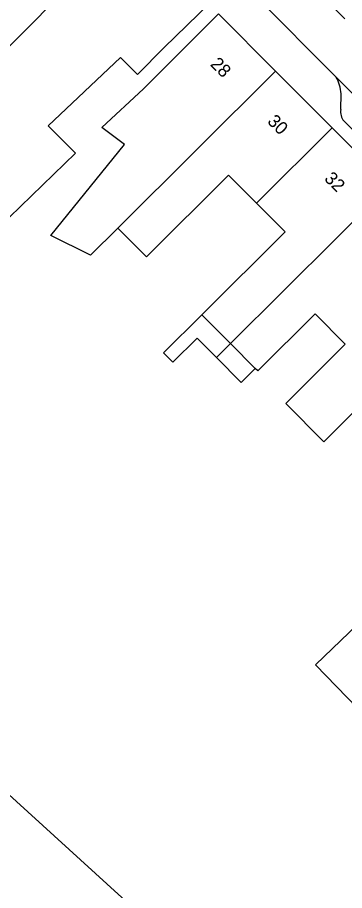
# Model space of a CAD drawing. Extents: x 160107 to 160928, y 382056 to 382918.
# Drawn here: x 160757.6 to 160782.8, y 382664.5 to 382731.9 of the extents above; entities that cross this region are included whole.
import ezdxf

# ---------------------------------------------------------------- set-up
doc = ezdxf.new("R2010")
doc.units = 0
for name, color, linetype in [('IMGEO_Pand', 7, 'Continuous'), ('IMGEO_Pand_nummerreeks', 7, 'Continuous'), ('IMGEO_Rijbaan_lokaal_open', 7, 'Continuous'), ('IMGEO_Voetpad_open', 7, 'Continuous')]:
    doc.layers.add(name, color=color, linetype=linetype)

msp = doc.modelspace()

# ---------------------------------------------------------------- linework, layer by layer
at = {"layer": 'IMGEO_Pand'}
for points in [[(160764.24, 382737.062), (160754.525, 382727.294)], [(160772.42, 382733.035), (160768.898, 382729.596), (160766.833, 382727.519), (160765.518, 382728.827), (160759.935, 382723.549), (160762.058, 382721.439), (160754.39, 382714.036), (160747.829, 382720.785), (160752.573, 382725.396)], [(160765.325, 382715.66), (160763.224, 382713.568), (160760.151, 382715.087), (160765.841, 382722.115), (160764.083, 382723.432), (160767.295, 382726.41), (160769.641, 382728.746), (160773.112, 382732.203)], [(160773.112, 382732.203), (160777.507, 382727.789)], [(160765.325, 382715.66), (160777.507, 382727.789)], [(160777.507, 382727.789), (160781.87, 382723.407)], [(160781.87, 382723.407), (160776.027, 382717.589)], [(160781.87, 382723.407), (160786.299, 382718.959)], [(160776.027, 382717.589), (160773.877, 382719.748), (160767.538, 382713.437), (160765.325, 382715.66)], [(160786.299, 382718.959), (160774.026, 382706.739)], [(160771.813, 382708.961), (160778.244, 382715.363), (160776.027, 382717.589)], [(160772.944, 382705.661), (160771.446, 382707.166), (160769.568, 382705.296), (160768.853, 382706.014), (160771.813, 382708.961)], [(160774.026, 382706.739), (160771.813, 382708.961)], [(160782.896, 382706.698), (160780.563, 382709.041), (160776.129, 382704.626), (160775.945, 382704.811)], [(160795.983, 382709.146), (160790.192, 382703.379), (160788.26, 382705.349), (160786.899, 382703.994), (160785.746, 382705.151), (160784.659, 382704.069), (160785.41, 382703.315), (160781.245, 382699.163), (160778.301, 382702.117), (160780.645, 382704.454), (160782.896, 382706.698)], [(160774.026, 382706.739), (160772.944, 382705.661)], [(160775.945, 382704.811), (160774.026, 382706.739)], [(160775.945, 382704.811), (160774.863, 382703.733), (160772.944, 382705.661)], [(160730.83, 382683.568), (160736.85, 382690.176), (160769.696, 382660.249), (160763.676, 382653.641), (160730.83, 382683.568)], [(160783.828, 382685.04), (160787.066, 382681.691), (160783.843, 382678.575), (160780.606, 382681.923), (160783.828, 382685.04)]]:
    msp.add_lwpolyline(points, dxfattribs=at)
at = {"layer": 'IMGEO_Rijbaan_lokaal_open'}
for points in [[(160782.85, 382731.824), (160777.128, 382737.621)], [(160775.974, 382733.572), (160782.193, 382727.326)], [(160782.193, 382727.326), (160800.958, 382708.481)]]:
    msp.add_lwpolyline(points, dxfattribs=at)
at = {"layer": 'IMGEO_Voetpad_open'}
for points in [[(160782.554, 382724.819), (160782.581, 382726.025)], [(160797.543, 382709.024), (160782.794, 382723.93)]]:
    msp.add_lwpolyline(points, dxfattribs=at)
for centre, radius, start, end in [((160779.269, 382725.746), 3.323, 4.82032, 28.39222), ((160783.518, 382724.602), 0.988, 167.32041, 222.89514)]:
    msp.add_arc(centre, radius, start, end, dxfattribs=at)

# ---------------------------------------------------------------- texts
at = {"layer": 'IMGEO_Pand_nummerreeks'}
for s, rotation, p in [('28', 314.87384, (160772.409, 382728.26)), ('30', 314.87508, (160776.814, 382723.835)), ('32', 314.87508, (160781.214, 382719.415))]:
    msp.add_text(s, height=1, rotation=rotation, dxfattribs=at).set_placement(p)

doc.saveas('drawing.dxf')
